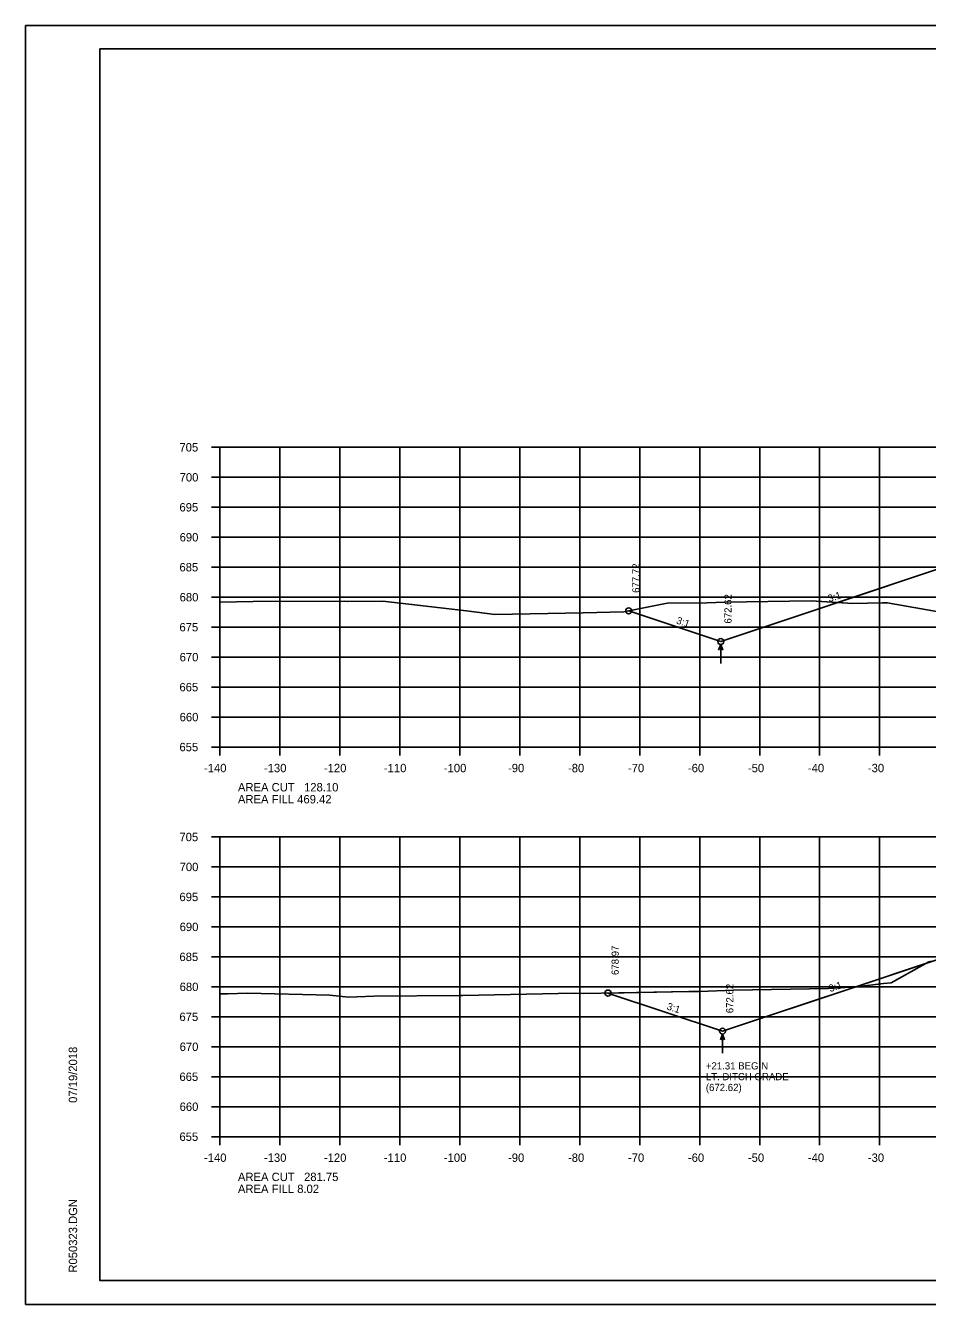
# Model space of a CAD drawing. Extents: x 1360146 to 1361431, y 631444 to 632352.
# Drawn here: x 1360146.4 to 1360296.7, y 631657.5 to 631870.8 of the extents above; entities that cross this region are included whole.
import ezdxf

# ---------------------------------------------------------------- set-up
doc = ezdxf.new("R2010")
doc.units = 0
for name, color, linetype in [('Default', 7, 'Continuous'), ('R_Axis', 7, 'Continuous'), ('R_Axis Annot', 7, 'Continuous'), ('R_Border', 7, 'Continuous'), ('R_Exist Surface', 7, 'Continuous'), ('R_Fin Surface', 7, 'Continuous'), ('R_Grid', 7, 'Continuous'), ('R_No Plot', 7, 'Continuous'), ('R_Water Annot', 7, 'Continuous'), ('R_Xsect Elev', 7, 'Continuous'), ('R_Xsect Slope', 7, 'Continuous')]:
    doc.layers.add(name, color=color, linetype=linetype)

msp = doc.modelspace()

# ---------------------------------------------------------------- linework, layer by layer
at = {"layer": 'R_Axis'}
for p, q in [((1360177.37, 631800.48), (1360178.77, 631800.48)), ((1360178.77, 631750.48), (1360178.77, 631800.48)), ((1360177.37, 631795.48), (1360178.77, 631795.48)), ((1360177.37, 631790.48), (1360178.77, 631790.48)), ((1360177.37, 631785.48), (1360178.77, 631785.48)), ((1360177.37, 631780.48), (1360178.77, 631780.48)), ((1360177.37, 631775.48), (1360178.77, 631775.48)), ((1360177.37, 631770.48), (1360178.77, 631770.48)), ((1360177.37, 631765.48), (1360178.77, 631765.48)), ((1360177.37, 631760.48), (1360178.77, 631760.48)), ((1360177.37, 631755.48), (1360178.77, 631755.48)), ((1360177.37, 631750.48), (1360178.77, 631750.48)), ((1360178.77, 631750.48), (1360458.77, 631750.48)), ((1360178.77, 631749.08), (1360178.77, 631750.48)), ((1360188.77, 631749.08), (1360188.77, 631750.48)), ((1360198.77, 631749.08), (1360198.77, 631750.48)), ((1360208.77, 631749.08), (1360208.77, 631750.48)), ((1360218.77, 631749.08), (1360218.77, 631750.48)), ((1360228.77, 631749.08), (1360228.77, 631750.48)), ((1360238.77, 631749.08), (1360238.77, 631750.48)), ((1360248.77, 631749.08), (1360248.77, 631750.48)), ((1360258.77, 631749.08), (1360258.77, 631750.48)), ((1360268.77, 631749.08), (1360268.77, 631750.48)), ((1360278.77, 631749.08), (1360278.77, 631750.48)), ((1360288.77, 631749.08), (1360288.77, 631750.48)), ((1360177.37, 631735.48), (1360178.77, 631735.48)), ((1360178.77, 631685.48), (1360178.77, 631735.48)), ((1360177.37, 631730.48), (1360178.77, 631730.48)), ((1360177.37, 631725.48), (1360178.77, 631725.48)), ((1360177.37, 631720.48), (1360178.77, 631720.48)), ((1360177.37, 631715.48), (1360178.77, 631715.48)), ((1360177.37, 631710.48), (1360178.77, 631710.48)), ((1360177.37, 631705.48), (1360178.77, 631705.48)), ((1360177.37, 631700.48), (1360178.77, 631700.48)), ((1360177.37, 631695.48), (1360178.77, 631695.48)), ((1360177.37, 631690.48), (1360178.77, 631690.48)), ((1360177.37, 631685.48), (1360178.77, 631685.48)), ((1360178.77, 631685.48), (1360458.77, 631685.48)), ((1360178.77, 631684.08), (1360178.77, 631685.48)), ((1360188.77, 631684.08), (1360188.77, 631685.48)), ((1360198.77, 631684.08), (1360198.77, 631685.48)), ((1360208.77, 631684.08), (1360208.77, 631685.48)), ((1360218.77, 631684.08), (1360218.77, 631685.48)), ((1360228.77, 631684.08), (1360228.77, 631685.48)), ((1360238.77, 631684.08), (1360238.77, 631685.48)), ((1360248.77, 631684.08), (1360248.77, 631685.48)), ((1360258.77, 631684.08), (1360258.77, 631685.48)), ((1360268.77, 631684.08), (1360268.77, 631685.48)), ((1360278.77, 631684.08), (1360278.77, 631685.48)), ((1360288.77, 631684.08), (1360288.77, 631685.48))]:
    msp.add_line(p, q, dxfattribs=at)
at = {"layer": 'R_Border'}
for p, q in [((1360158.77, 631866.94), (1360474.95, 631866.94)), ((1360158.77, 631661.48), (1360158.77, 631866.94)), ((1360158.77, 631661.48), (1360158.77, 631661.48)), ((1360474.95, 631661.48), (1360158.77, 631661.48))]:
    msp.add_line(p, q, dxfattribs=at)
at = {"layer": 'R_Exist Surface'}
for points in [[(1360178.77, 631774.65), (1360184.33, 631774.74), (1360199.62, 631774.83), (1360200.07, 631774.78), (1360205.95, 631774.84), (1360219.9, 631773.18), (1360224.59, 631772.62), (1360239.34, 631772.85), (1360246.13, 631773.05), (1360253.33, 631774.46), (1360259.94, 631774.52), (1360262.94, 631774.63), (1360277.35, 631774.89), (1360284.25, 631774.44), (1360289.25, 631774.55), (1360290.04, 631774.56), (1360290.37, 631774.5), (1360298.93, 631772.97)], [(1360178.77, 631709.34), (1360180.04, 631709.3), (1360183.34, 631709.42), (1360197.09, 631709.08), (1360200.21, 631708.77), (1360204.43, 631708.95), (1360218.74, 631709.02), (1360219.25, 631709.03), (1360237.85, 631709.42), (1360239.43, 631709.38), (1360256.93, 631709.69), (1360258.8, 631709.7), (1360264.38, 631709.9), (1360280.27, 631710.21), (1360284.89, 631710.5), (1360289.43, 631711.01), (1360290.7, 631711.15), (1360295.86, 631714.04), (1360296.98, 631714.63)]]:
    msp.add_lwpolyline(points, dxfattribs=at)
at = {"layer": 'R_Fin Surface'}
for points in [[(1360246.93, 631773.2), (1360262.28, 631768.08), (1360298.75, 631780.24), (1360298.77, 631780.24), (1360304.77, 631781.74), (1360308.77, 631781.44), (1360318.77, 631780.68), (1360328.77, 631779.92), (1360332.77, 631779.61), (1360338.55, 631778.17), (1360338.77, 631778.11), (1360364.97, 631769.38), (1360369.61, 631770.93)], [(1360243.47, 631709.45), (1360262.57, 631703.08), (1360297.47, 631714.72), (1360297.48, 631714.72), (1360297.49, 631714.72), (1360297.49, 631714.72), (1360298.75, 631715.14), (1360298.77, 631715.15), (1360304.77, 631716.65), (1360308.77, 631716.34), (1360318.77, 631715.58), (1360328.77, 631714.82), (1360332.77, 631714.52), (1360338.55, 631713.07), (1360338.77, 631713.02), (1360364.68, 631704.38), (1360381.82, 631710.1)]]:
    msp.add_lwpolyline(points, dxfattribs=at)
at = {"layer": 'R_Grid'}
for p, q in [((1360178.77, 631800.48), (1360458.77, 631800.48)), ((1360178.77, 631750.48), (1360178.77, 631800.48)), ((1360188.77, 631750.48), (1360188.77, 631800.48)), ((1360198.77, 631750.48), (1360198.77, 631800.48)), ((1360208.77, 631750.48), (1360208.77, 631800.48)), ((1360218.77, 631750.48), (1360218.77, 631800.48)), ((1360228.77, 631750.48), (1360228.77, 631800.48)), ((1360238.77, 631750.48), (1360238.77, 631800.48)), ((1360248.77, 631750.48), (1360248.77, 631800.48)), ((1360258.77, 631750.48), (1360258.77, 631800.48)), ((1360268.77, 631750.48), (1360268.77, 631800.48)), ((1360278.77, 631750.48), (1360278.77, 631800.48)), ((1360288.77, 631750.48), (1360288.77, 631800.48)), ((1360178.77, 631795.48), (1360458.77, 631795.48)), ((1360178.77, 631790.48), (1360458.77, 631790.48)), ((1360178.77, 631785.48), (1360458.77, 631785.48)), ((1360178.77, 631780.48), (1360458.77, 631780.48)), ((1360178.77, 631775.48), (1360458.77, 631775.48)), ((1360178.77, 631770.48), (1360458.77, 631770.48)), ((1360178.77, 631765.48), (1360458.77, 631765.48)), ((1360178.77, 631760.48), (1360458.77, 631760.48)), ((1360178.77, 631755.48), (1360458.77, 631755.48)), ((1360178.77, 631750.48), (1360458.77, 631750.48)), ((1360178.77, 631735.48), (1360458.77, 631735.48)), ((1360178.77, 631685.48), (1360178.77, 631735.48)), ((1360188.77, 631685.48), (1360188.77, 631735.48)), ((1360198.77, 631685.48), (1360198.77, 631735.48)), ((1360208.77, 631685.48), (1360208.77, 631735.48)), ((1360218.77, 631685.48), (1360218.77, 631735.48)), ((1360228.77, 631685.48), (1360228.77, 631735.48)), ((1360238.77, 631685.48), (1360238.77, 631735.48)), ((1360248.77, 631685.48), (1360248.77, 631735.48)), ((1360258.77, 631685.48), (1360258.77, 631735.48)), ((1360268.77, 631685.48), (1360268.77, 631735.48)), ((1360278.77, 631685.48), (1360278.77, 631735.48)), ((1360288.77, 631685.48), (1360288.77, 631735.48)), ((1360178.77, 631730.48), (1360458.77, 631730.48)), ((1360178.77, 631725.48), (1360458.77, 631725.48)), ((1360178.77, 631720.48), (1360458.77, 631720.48)), ((1360178.77, 631715.48), (1360458.77, 631715.48)), ((1360178.77, 631710.48), (1360458.77, 631710.48)), ((1360178.77, 631705.48), (1360458.77, 631705.48)), ((1360178.77, 631700.48), (1360458.77, 631700.48)), ((1360178.77, 631695.48), (1360458.77, 631695.48)), ((1360178.77, 631690.48), (1360458.77, 631690.48)), ((1360178.77, 631685.48), (1360458.77, 631685.48))]:
    msp.add_line(p, q, dxfattribs=at)
at = {"layer": 'R_No Plot'}
for p, q in [((1360146.37, 631870.84), (1360479.7, 631870.84)), ((1360146.37, 631657.5), (1360479.7, 631657.5))]:
    msp.add_line(p, q, dxfattribs=at)
for points in [[(1360146.36, 631870.84), (1360479.7, 631870.84), (1360479.7, 631657.5), (1360146.36, 631657.5)], [(1360392.69, 631866.94), (1360392.69, 631857.06), (1360428.42, 631857.06), (1360428.42, 631854.14), (1360451.62, 631854.14), (1360451.62, 631829.81), (1360474.95, 631829.81), (1360474.95, 631661.48), (1360158.77, 631661.48), (1360158.77, 631866.94)], [(1360246.93, 631773.2), (1360253.33, 631774.46), (1360259.94, 631774.52), (1360262.94, 631774.63), (1360277.35, 631774.89), (1360281.82, 631774.6), (1360262.28, 631768.08)], [(1360284.8, 631710.49), (1360284.89, 631710.5), (1360289.43, 631711.01), (1360290.7, 631711.15), (1360295.86, 631714.04), (1360296.58, 631714.42)], [(1360296.58, 631714.42), (1360296.98, 631714.63), (1360297.2, 631714.68), (1360297.49, 631714.72), (1360297.48, 631714.72), (1360297.47, 631714.72)], [(1360243.47, 631709.45), (1360256.93, 631709.69), (1360258.8, 631709.7), (1360264.38, 631709.9), (1360280.27, 631710.21), (1360284.8, 631710.49), (1360262.57, 631703.08)]]:
    msp.add_lwpolyline(points, close=True, dxfattribs=at)
msp.add_lwpolyline([(1360298.75, 631780.24), (1360281.82, 631774.6), (1360284.25, 631774.44), (1360289.25, 631774.55), (1360290.04, 631774.56), (1360290.37, 631774.5), (1360298.93, 631772.97)], dxfattribs=at)
for centre in [(1360246.93, 631773.2), (1360262.28, 631768.08), (1360243.47, 631709.45), (1360262.57, 631703.08)]:
    msp.add_circle(centre, 0.5, dxfattribs=at)
at = {"layer": 'R_Water Annot'}
for p, q in [((1360262.28, 631767.58), (1360261.93, 631766.62)), ((1360262.28, 631764.44), (1360262.28, 631767.58)), ((1360262.28, 631767.58), (1360262.63, 631766.62)), ((1360262.57, 631702.58), (1360262.22, 631701.62)), ((1360262.57, 631699.44), (1360262.57, 631702.58)), ((1360262.57, 631702.58), (1360262.92, 631701.62))]:
    msp.add_line(p, q, dxfattribs=at)

# ---------------------------------------------------------------- texts
at = {"layer": 'Default'}
for s, p in [('+21.31 BEGIN', (1360259.79, 631696.7)), ('LT. DITCH GRADE', (1360259.79, 631694.9)), ('(672.62)', (1360259.79, 631693.1))]:
    msp.add_text(s, height=1.2, dxfattribs=at).set_placement(p)
at = {"layer": 'R_Axis Annot'}
for s, p in [('705', (1360172.02, 631799.78)), ('700', (1360172.05, 631794.78)), ('695', (1360172.02, 631789.78)), ('690', (1360172.05, 631784.78)), ('685', (1360172.02, 631779.78)), ('680', (1360172.05, 631774.78)), ('675', (1360172.02, 631769.78)), ('670', (1360172.05, 631764.78)), ('665', (1360172.02, 631759.78)), ('660', (1360172.05, 631754.78)), ('655', (1360172.02, 631749.78)), ('-140', (1360176.11, 631746.28)), ('-130', (1360186.11, 631746.28)), ('-120', (1360196.11, 631746.28)), ('-110', (1360206.11, 631746.28)), ('-100', (1360216.11, 631746.28)), ('-90', (1360226.81, 631746.28)), ('-80', (1360236.81, 631746.28)), ('-70', (1360246.81, 631746.28)), ('-60', (1360256.81, 631746.28)), ('-50', (1360266.81, 631746.28)), ('-40', (1360276.81, 631746.28)), ('-30', (1360286.81, 631746.28)), ('AREA CUT   128.10', (1360181.77, 631743.08)), ('AREA FILL 469.42', (1360181.77, 631741.08)), ('705', (1360172.02, 631734.78)), ('700', (1360172.05, 631729.78)), ('695', (1360172.02, 631724.78)), ('690', (1360172.05, 631719.78)), ('685', (1360172.02, 631714.78)), ('680', (1360172.05, 631709.78)), ('675', (1360172.02, 631704.78)), ('670', (1360172.05, 631699.78)), ('665', (1360172.02, 631694.78)), ('660', (1360172.05, 631689.78)), ('655', (1360172.02, 631684.78)), ('-140', (1360176.11, 631681.28)), ('-130', (1360186.11, 631681.28)), ('-120', (1360196.11, 631681.28)), ('-110', (1360206.11, 631681.28)), ('-100', (1360216.11, 631681.28)), ('-90', (1360226.81, 631681.28)), ('-80', (1360236.81, 631681.28)), ('-70', (1360246.81, 631681.28)), ('-60', (1360256.81, 631681.28)), ('-50', (1360266.81, 631681.28)), ('-40', (1360276.81, 631681.28)), ('-30', (1360286.81, 631681.28)), ('AREA CUT   281.75', (1360181.77, 631678.08)), ('AREA FILL 8.02', (1360181.77, 631676.08))]:
    msp.add_text(s, height=1.4, dxfattribs=at).set_placement(p)
at = {"layer": 'R_Border'}
for s, p in [('07/19/2018', (1360154.96, 631691.12)), ('R050323.DGN', (1360154.96, 631662.81))]:
    msp.add_text(s, height=1.4, rotation=90, dxfattribs=at).set_placement(p)
at = {"layer": 'R_Xsect Elev'}
for s, p in [('677.72', (1360248.73, 631776.2)), ('672.62', (1360264.08, 631771.08)), ('678.97', (1360245.27, 631712.45)), ('672.62', (1360264.37, 631706.08))]:
    msp.add_text(s, height=1.2, rotation=90, dxfattribs=at).set_placement(p)
at = {"layer": 'R_Xsect Slope'}
for rotation, p in [(18.4349, (1360280.37, 631774.64)), (341.5651, (1360254.76, 631771.12)), (18.4349, (1360280.51, 631709.59)), (341.5651, (1360253.18, 631706.74))]:
    msp.add_text('3:1', height=1.2, rotation=rotation, dxfattribs=at).set_placement(p)

doc.saveas('drawing.dxf')
